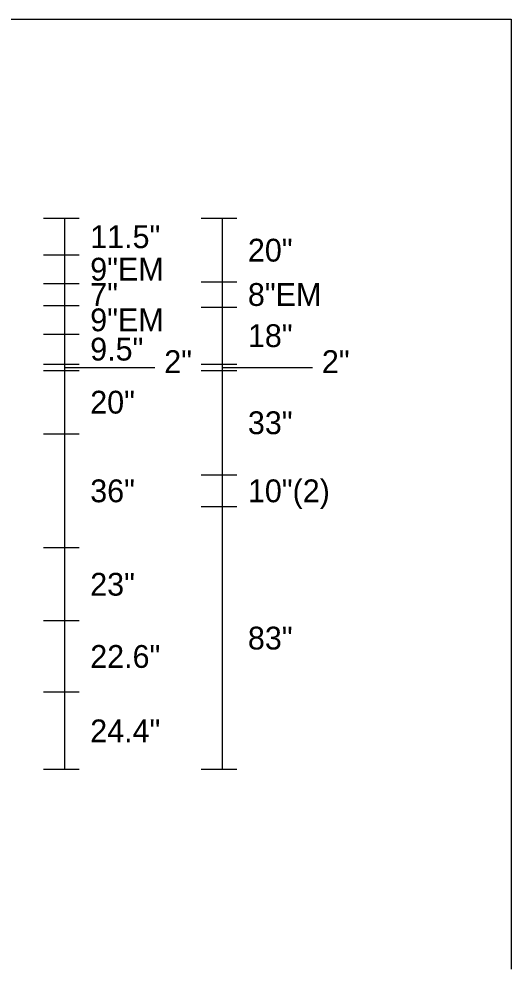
# Model space of a CAD drawing. Extents: x 10268259 to 10268554, y 2141099 to 2141249.
# Drawn here: x 10268455.43 to 10268470.98, y 2141125.53 to 2141155.53 of the extents above; entities that cross this region are included whole.
import ezdxf

# ---------------------------------------------------------------- set-up
doc = ezdxf.new("R2010")
doc.units = 0
doc.layers.add('60', color=7, linetype='Continuous')
doc.layers.add('GSDims', color=7, linetype='Continuous')

msp = doc.modelspace()

# ---------------------------------------------------------------- linework, layer by layer
at = {"layer": '60'}
for p, q in [((10268418.73, 2141155.528), (10268470.98, 2141155.528)), ((10268470.98, 2141155.528), (10268470.98, 2141125.528))]:
    msp.add_line(p, q, dxfattribs=at)
at = {"layer": 'GSDims'}
for p, q in [((10268457.333, 2141149.228), (10268456.208, 2141149.228)), ((10268456.883, 2141131.828), (10268456.883, 2141149.228)), ((10268462.316, 2141149.228), (10268461.191, 2141149.228)), ((10268461.866, 2141131.828), (10268461.866, 2141149.228)), ((10268456.208, 2141148.078), (10268457.333, 2141148.078)), ((10268461.191, 2141147.228), (10268462.316, 2141147.228)), ((10268456.208, 2141147.178), (10268457.333, 2141147.178)), ((10268456.208, 2141146.478), (10268457.333, 2141146.478)), ((10268461.191, 2141146.428), (10268462.316, 2141146.428)), ((10268456.208, 2141145.578), (10268457.333, 2141145.578)), ((10268456.208, 2141144.628), (10268457.333, 2141144.628)), ((10268456.883, 2141144.528), (10268459.722, 2141144.528)), ((10268461.191, 2141144.628), (10268462.316, 2141144.628)), ((10268461.866, 2141144.528), (10268464.704, 2141144.528)), ((10268456.208, 2141144.428), (10268457.333, 2141144.428)), ((10268461.191, 2141144.428), (10268462.316, 2141144.428)), ((10268456.208, 2141142.428), (10268457.333, 2141142.428)), ((10268462.316, 2141141.128), (10268461.191, 2141141.128)), ((10268462.316, 2141140.128), (10268461.191, 2141140.128)), ((10268457.333, 2141138.828), (10268456.208, 2141138.828)), ((10268457.333, 2141136.528), (10268456.208, 2141136.528)), ((10268457.333, 2141134.268), (10268456.208, 2141134.268)), ((10268457.333, 2141131.828), (10268456.208, 2141131.828)), ((10268462.316, 2141131.828), (10268461.191, 2141131.828))]:
    msp.add_line(p, q, dxfattribs=at)

# ---------------------------------------------------------------- texts
for s, p in [('11.5"', (10268457.683, 2141148.293)), ('20"', (10268462.666, 2141147.868)), ('9"EM', (10268457.683, 2141147.268)), ('7"', (10268457.683, 2141146.468)), ('8"EM', (10268462.666, 2141146.468)), ('9"EM', (10268457.683, 2141145.668)), ('18"', (10268462.666, 2141145.168)), ('9.5"', (10268457.683, 2141144.743)), ('2"', (10268460.022, 2141144.348)), ('2"', (10268465.004, 2141144.348)), ('20"', (10268457.683, 2141143.068)), ('33"', (10268462.666, 2141142.418)), ('36"', (10268457.683, 2141140.268)), ('10"(2)', (10268462.666, 2141140.268)), ('23"', (10268457.683, 2141137.318)), ('83"', (10268462.666, 2141135.618)), ('22.6"', (10268457.683, 2141135.038)), ('24.4"', (10268457.683, 2141132.688))]:
    msp.add_text(s, height=0.72, dxfattribs=at).set_placement(p)

doc.saveas('drawing.dxf')
